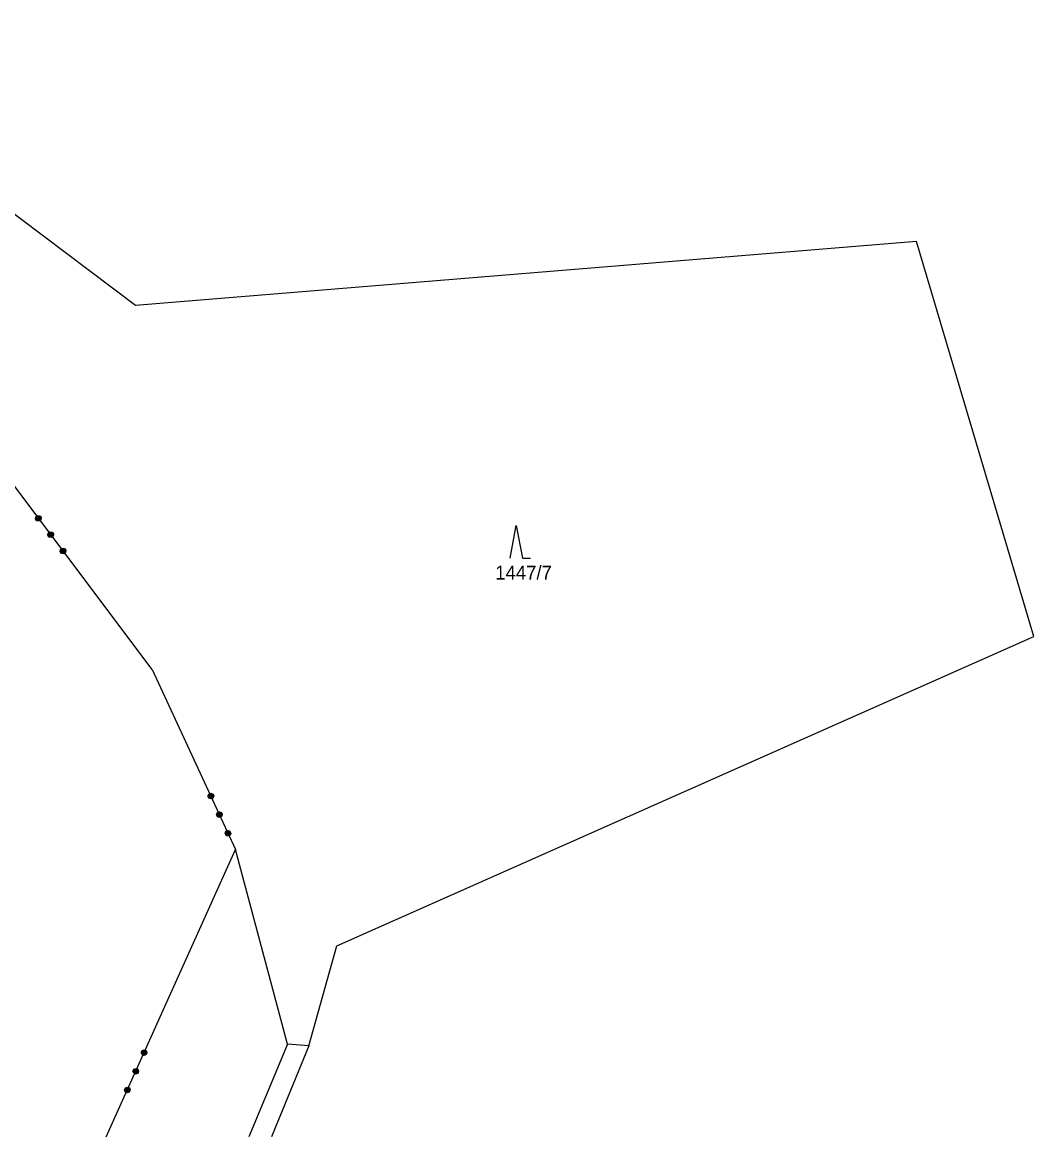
# Model space of a CAD drawing. Extents: x -779618 to -776429, y -1144546 to -1143350.
# Drawn here: x -779204.7 to -779080.7, y -1144546.2 to -1144409.6 of the extents above; entities that cross this region are included whole.
import ezdxf

# ---------------------------------------------------------------- set-up
doc = ezdxf.new("R2010")
doc.units = 0
for name, color, linetype in [('1', 7, 'Continuous'), ('2', 7, 'Continuous'), ('3', 7, 'Continuous')]:
    doc.layers.add(name, color=color, linetype=linetype)

msp = doc.modelspace()

# ---------------------------------------------------------------- linework, layer by layer
at = {"layer": '1'}
for p, q in [((-779190.82, -1144444.32), (-779236.88, -1144409.59)), ((-779095.09, -1144436.48), (-779190.82, -1144444.32)), ((-779080.73, -1144484.89), (-779095.09, -1144436.48)), ((-779188.79, -1144488.91), (-779213.67, -1144455.88)), ((-779166.16, -1144522.79), (-779080.73, -1144484.89)), ((-779188.79, -1144488.91), (-779178.56, -1144510.98)), ((-779194.42, -1144546.2), (-779178.56, -1144510.98)), ((-779172.2, -1144534.87), (-779178.56, -1144510.98)), ((-779169.59, -1144535.06), (-779166.16, -1144522.79)), ((-779172.2, -1144534.87), (-779176.92, -1144546.2)), ((-779169.59, -1144535.06), (-779174.14, -1144546.2)), ((-779169.59, -1144535.06), (-779172.2, -1144534.87))]:
    msp.add_line(p, q, dxfattribs=at)
for points in [[(-779203.08, -1144470.47), (-779203.04, -1144470.2), (-779202.83, -1144470.04), (-779202.56, -1144470.08), (-779202.4, -1144470.29), (-779202.44, -1144470.56), (-779202.65, -1144470.72), (-779202.92, -1144470.69), (-779203.08, -1144470.47), (-779203.02, -1144470.48), (-779202.88, -1144470.67), (-779202.78, -1144470.67), (-779203.01, -1144470.37), (-779202.99, -1144470.25), (-779202.68, -1144470.67), (-779202.62, -1144470.62), (-779202.93, -1144470.21), (-779202.86, -1144470.16), (-779202.55, -1144470.57), (-779202.48, -1144470.53), (-779202.79, -1144470.12), (-779202.71, -1144470.1), (-779202.46, -1144470.43), (-779202.43, -1144470.34), (-779202.57, -1144470.15)], [(-779201.57, -1144472.48), (-779201.53, -1144472.21), (-779201.32, -1144472.05), (-779201.05, -1144472.08), (-779200.89, -1144472.3), (-779200.93, -1144472.57), (-779201.14, -1144472.73), (-779201.41, -1144472.69), (-779201.57, -1144472.48), (-779201.53, -1144472.46), (-779201.39, -1144472.65), (-779201.28, -1144472.67), (-779201.52, -1144472.35), (-779201.5, -1144472.24), (-779201.16, -1144472.68), (-779201.1, -1144472.63), (-779201.44, -1144472.19), (-779201.37, -1144472.14), (-779201.04, -1144472.59), (-779200.97, -1144472.54), (-779201.31, -1144472.09), (-779201.2, -1144472.11), (-779200.96, -1144472.43), (-779200.94, -1144472.31), (-779201.08, -1144472.12)], [(-779200.06, -1144474.48), (-779200.02, -1144474.21), (-779199.81, -1144474.05), (-779199.54, -1144474.09), (-779199.38, -1144474.31), (-779199.42, -1144474.57), (-779199.63, -1144474.73), (-779199.9, -1144474.7), (-779200.06, -1144474.48), (-779200.03, -1144474.45), (-779199.89, -1144474.64), (-779199.78, -1144474.66), (-779200.02, -1144474.34), (-779199.99, -1144474.24), (-779199.67, -1144474.67), (-779199.6, -1144474.62), (-779199.92, -1144474.2), (-779199.86, -1144474.14), (-779199.54, -1144474.57), (-779199.48, -1144474.52), (-779199.8, -1144474.1), (-779199.71, -1144474.09), (-779199.45, -1144474.43), (-779199.42, -1144474.33), (-779199.59, -1144474.1)], [(-779181.24, -1144504.43), (-779181.33, -1144504.68), (-779181.58, -1144504.8), (-779181.83, -1144504.7), (-779181.95, -1144504.46), (-779181.85, -1144504.21), (-779181.61, -1144504.09), (-779181.36, -1144504.19), (-779181.24, -1144504.43), (-779181.27, -1144504.46), (-779181.37, -1144504.24), (-779181.48, -1144504.2), (-779181.31, -1144504.56), (-779181.36, -1144504.65), (-779181.59, -1144504.16), (-779181.66, -1144504.19), (-779181.44, -1144504.68), (-779181.51, -1144504.72), (-779181.73, -1144504.24), (-779181.8, -1144504.27), (-779181.58, -1144504.75), (-779181.67, -1144504.74), (-779181.85, -1144504.35), (-779181.9, -1144504.45), (-779181.78, -1144504.7)], [(-779180.19, -1144506.71), (-779180.28, -1144506.96), (-779180.52, -1144507.07), (-779180.78, -1144506.98), (-779180.89, -1144506.74), (-779180.8, -1144506.48), (-779180.55, -1144506.37), (-779180.3, -1144506.46), (-779180.19, -1144506.71), (-779180.23, -1144506.72), (-779180.33, -1144506.5), (-779180.43, -1144506.46), (-779180.27, -1144506.82), (-779180.31, -1144506.93), (-779180.54, -1144506.42), (-779180.61, -1144506.45), (-779180.38, -1144506.96), (-779180.45, -1144507), (-779180.69, -1144506.49), (-779180.76, -1144506.52), (-779180.52, -1144507.03), (-779180.63, -1144506.99), (-779180.8, -1144506.63), (-779180.84, -1144506.73), (-779180.74, -1144506.95)], [(-779179.13, -1144508.99), (-779179.23, -1144509.24), (-779179.47, -1144509.35), (-779179.72, -1144509.26), (-779179.84, -1144509.01), (-779179.74, -1144508.76), (-779179.5, -1144508.65), (-779179.25, -1144508.74), (-779179.13, -1144508.99), (-779179.19, -1144508.97), (-779179.29, -1144508.75), (-779179.38, -1144508.73), (-779179.22, -1144509.07), (-779179.26, -1144509.18), (-779179.48, -1144508.71), (-779179.55, -1144508.74), (-779179.34, -1144509.21), (-779179.41, -1144509.25), (-779179.63, -1144508.77), (-779179.7, -1144508.8), (-779179.49, -1144509.27), (-779179.58, -1144509.27), (-779179.75, -1144508.9), (-779179.8, -1144508.98), (-779179.7, -1144509.19)], [(-779190.01, -1144535.63), (-779189.76, -1144535.53), (-779189.51, -1144535.64), (-779189.42, -1144535.89), (-779189.53, -1144536.14), (-779189.78, -1144536.24), (-779190.02, -1144536.12), (-779190.12, -1144535.87), (-779190.01, -1144535.63), (-779189.99, -1144535.68), (-779190.09, -1144535.9), (-779190.04, -1144535.99), (-779189.88, -1144535.64), (-779189.78, -1144535.6), (-779189.99, -1144536.07), (-779189.92, -1144536.11), (-779189.7, -1144535.63), (-779189.63, -1144535.67), (-779189.85, -1144536.14), (-779189.78, -1144536.18), (-779189.56, -1144535.71), (-779189.51, -1144535.78), (-779189.67, -1144536.15), (-779189.58, -1144536.14), (-779189.48, -1144535.92)], [(-779191.04, -1144537.92), (-779190.79, -1144537.82), (-779190.54, -1144537.93), (-779190.45, -1144538.18), (-779190.56, -1144538.43), (-779190.81, -1144538.52), (-779191.05, -1144538.41), (-779191.15, -1144538.16), (-779191.04, -1144537.92), (-779191.01, -1144537.94), (-779191.11, -1144538.16), (-779191.07, -1144538.27), (-779190.9, -1144537.9), (-779190.8, -1144537.86), (-779191.03, -1144538.37), (-779190.95, -1144538.4), (-779190.72, -1144537.89), (-779190.65, -1144537.93), (-779190.88, -1144538.44), (-779190.81, -1144538.47), (-779190.58, -1144537.96), (-779190.54, -1144538.07), (-779190.7, -1144538.43), (-779190.59, -1144538.39), (-779190.5, -1144538.17)], [(-779192.07, -1144540.21), (-779191.82, -1144540.11), (-779191.57, -1144540.22), (-779191.48, -1144540.47), (-779191.59, -1144540.72), (-779191.84, -1144540.81), (-779192.08, -1144540.7), (-779192.18, -1144540.45), (-779192.07, -1144540.21), (-779192.03, -1144540.21), (-779192.13, -1144540.43), (-779192.09, -1144540.54), (-779191.92, -1144540.17), (-779191.83, -1144540.15), (-779192.05, -1144540.64), (-779191.97, -1144540.68), (-779191.76, -1144540.19), (-779191.68, -1144540.22), (-779191.9, -1144540.7), (-779191.82, -1144540.73), (-779191.61, -1144540.25), (-779191.55, -1144540.33), (-779191.73, -1144540.72), (-779191.63, -1144540.69), (-779191.51, -1144540.43)]]:
    msp.add_lwpolyline(points, dxfattribs=at)
at = {"layer": '3'}
msp.add_lwpolyline([(-779144.91, -1144475.26), (-779144.16, -1144471.26), (-779143.41, -1144475.26), (-779142.41, -1144475.26)], dxfattribs=at)

# ---------------------------------------------------------------- texts
at = {"layer": '2'}
msp.add_text('1447/7', height=1.7, dxfattribs=at).set_placement((-779146.74, -1144477.9))

doc.saveas('drawing.dxf')
